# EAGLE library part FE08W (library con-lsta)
FEMALE HEADER
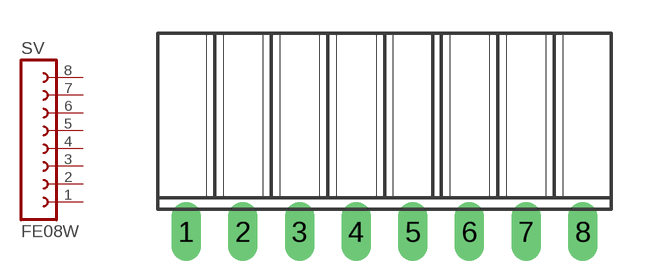
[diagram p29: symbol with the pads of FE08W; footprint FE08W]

Designator prefix SV

## FE08W (OC_FARNELL: unknown; OC_NEWARK: unknown)  [FE08W]
1  1  pas
2  2  pas
3  3  pas
4  4  pas
5  5  pas
6  6  pas
7  7  pas
8  8  pas

## Footprint FE08W (pad centres in mm)
FEMALE HEADER
drill 0.813 long: 1 -8.89,0; 2 -6.35,0; 3 -3.81,0; 4 -1.27,0; 5 1.27,0; 6 3.81,0; 7 6.35,0; 8 8.89,0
